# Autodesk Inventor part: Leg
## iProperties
Created: 2006-11
Part Number: Leg
Document SubType Name: Modeling
Designer: nfjf
Author: nfjf
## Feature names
1. Extrusion1
2. Fillet1
3. Fillet2
4. Extrusion2
